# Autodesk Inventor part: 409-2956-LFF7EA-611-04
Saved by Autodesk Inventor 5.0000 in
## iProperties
Created: 2010-06
Part Number: 409-2956-LFF7EA-611-04
Cost Center: 0 lbmass
Material: A36 STEEL PLATE
Document SubType Name: Sheet Metal
Designer: S. Boerckel
Authority: 0 in^3
Mass: 57707.5 g
Surface Area: 11978.2 cm^2
Volume: 7341.92 cm^3
Density: 7.86 g/cm^3
Flat Pattern Width: 51.435 cm
Flat Pattern Length: 112.395 cm
Flat Pattern Area: 5781.04 cm^2
Sheet Metal Rule: 1/2"Thk
Sheet Metal Width: 16.0000 in
Sheet Metal Length: 80.0000 in^2
Description: PUMP FOOT PLATE
User Status: BURN
SaveDate: 2008-01-15
SaveTime: 10:24
FileName: Sheet Metal
Wide: =<Flat Pattern Width>cm
Length: =<Flat Pattern Length>cm
Thickness: 0.5000 in
SMR: =<Sheet Metal Rule> - <Material>
Author: S. Boerckel
Revision Number: 0
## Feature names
1. Hole1
2. Plate1
